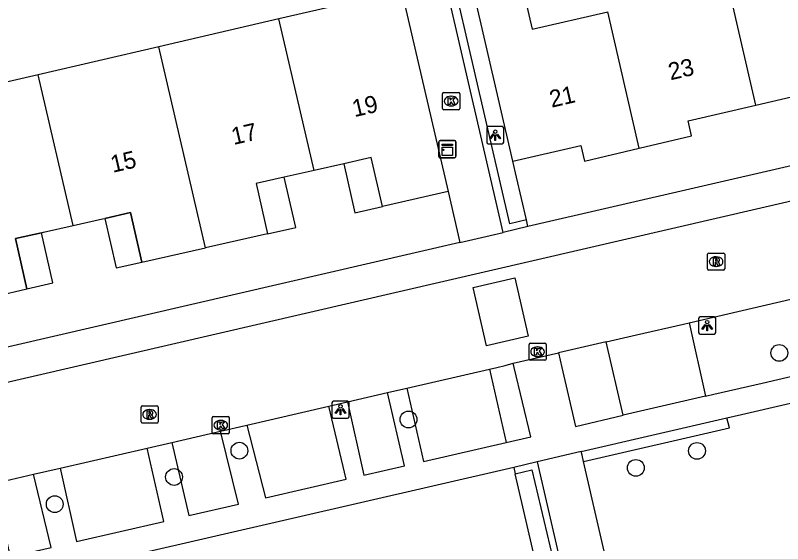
# Model space of a CAD drawing. Extents: x 156414 to 157775, y 382335 to 383765.
# Drawn here: x 156765.29 to 156810.03, y 382739.73 to 382770.51 of the extents above; entities that cross this region are included whole.
import ezdxf

# ---------------------------------------------------------------- set-up
doc = ezdxf.new("R2010")
doc.units = 0
for name, color, linetype in [('IMGEO_Boom', 7, 'Continuous'), ('IMGEO_Groenvoorziening', 7, 'Continuous'), ('IMGEO_Haag', 7, 'Continuous'), ('IMGEO_Kast', 7, 'Continuous'), ('IMGEO_Kolk', 7, 'Continuous'), ('IMGEO_Lichtpunt', 7, 'Continuous'), ('IMGEO_Muur', 7, 'Continuous'), ('IMGEO_Pand', 7, 'Continuous'), ('IMGEO_Pand_nummerreeks', 7, 'Continuous'), ('IMGEO_Pand_overbouw', 7, 'Continuous'), ('IMGEO_Parkeervlak_open', 7, 'Continuous'), ('IMGEO_Rijbaan_lokaal_gesloten', 7, 'Continuous'), ('IMGEO_Rijbaan_lokaal_open', 7, 'Continuous'), ('IMGEO_Rioolput', 7, 'Continuous'), ('IMGEO_Voetpad_open', 7, 'Continuous')]:
    doc.layers.add(name, color=color, linetype=linetype)

msp = doc.modelspace()

# ---------------------------------------------------------------- linework, layer by layer
at = {"layer": 'IMGEO_Boom'}
for centre in [(156809.836, 382750.839), (156788.215, 382746.96), (156778.352, 382745.143), (156805.037, 382745.131), (156801.469, 382744.14), (156774.54, 382743.611), (156767.583, 382742.024)]:
    msp.add_circle(centre, 0.489, dxfattribs=at)
at = {"layer": 'IMGEO_Groenvoorziening'}
for points in [[(156795.092, 382758.591), (156794.513, 382761.091), (156794.298, 382762.018)], [(156795.633, 382738.617), (156794.426, 382743.797)]]:
    msp.add_lwpolyline(points, dxfattribs=at)
at = {"layer": 'IMGEO_Haag'}
msp.add_lwpolyline([(156798.417, 382744.512), (156806.927, 382746.477), (156806.778, 382747.058)], dxfattribs=at)
at = {"layer": 'IMGEO_Kast'}
for p, q in [((156790.052, 382763.213), (156790.893, 382763.213)), ((156790.893, 382763.213), (156790.052, 382763.213)), ((156789.977, 382762.288), (156789.977, 382763.129)), ((156789.977, 382763.129), (156789.977, 382762.288)), ((156790.977, 382763.138), (156790.977, 382762.297)), ((156790.977, 382762.297), (156790.977, 382763.138)), ((156790.902, 382762.213), (156790.061, 382762.213)), ((156790.061, 382762.213), (156790.902, 382762.213))]:
    msp.add_line(p, q, dxfattribs=at)
for points in [[(156790.172, 382763.003), (156790.772, 382763.003), (156790.772, 382762.918), (156790.172, 382762.918), (156790.172, 382763.003)], [(156790.172, 382762.828), (156790.772, 382762.828), (156790.772, 382762.339), (156790.172, 382762.339), (156790.172, 382762.828)]]:
    msp.add_lwpolyline(points, dxfattribs=at)
msp.add_circle((156790.256, 382762.677), 0.0377, dxfattribs=at)
for centre, start, end in [((156790.055, 382763.135), 92.4484, 184.2845), ((156790.055, 382763.135), 92.4484, 184.2845), ((156790.899, 382763.135), 2.4484, 94.2845), ((156790.899, 382763.135), 2.4484, 94.2845), ((156790.055, 382762.291), 182.4484, 274.2845), ((156790.055, 382762.291), 182.4484, 274.2845), ((156790.899, 382762.291), 272.4484, 4.2845), ((156790.899, 382762.291), 272.4484, 4.2845)]:
    msp.add_arc(centre, 0.0779, start, end, dxfattribs=at)
at = {"layer": 'IMGEO_Kolk'}
for p, q in [((156790.199, 382765.088), (156790.199, 382765.94)), ((156790.274, 382766.014), (156791.126, 382766.014)), ((156791.2, 382765.94), (156791.2, 382765.088)), ((156790.687, 382765.794), (156790.712, 382765.794)), ((156791.126, 382765.014), (156790.274, 382765.014)), ((156790.71, 382765.234), (156790.685, 382765.234)), ((156795.243, 382750.484), (156795.243, 382751.336)), ((156795.318, 382751.41), (156796.17, 382751.41)), ((156795.731, 382751.19), (156795.756, 382751.19)), ((156796.244, 382751.336), (156796.244, 382750.484)), ((156796.17, 382750.41), (156795.318, 382750.41)), ((156795.754, 382750.63), (156795.729, 382750.63)), ((156776.839, 382747.129), (156777.691, 382747.129)), ((156776.764, 382746.203), (156776.764, 382747.055)), ((156777.252, 382746.909), (156777.277, 382746.909)), ((156777.765, 382747.055), (156777.765, 382746.203)), ((156777.275, 382746.349), (156777.25, 382746.349)), ((156777.691, 382746.129), (156776.839, 382746.129))]:
    msp.add_line(p, q, dxfattribs=at)
for points in [[(156790.199, 382765.088), (156790.199, 382765.94)], [(156790.274, 382766.014), (156791.126, 382766.014)], [(156791.2, 382765.94), (156791.2, 382765.088)], [(156790.52, 382765.714), (156790.643, 382765.714), (156790.643, 382765.563), (156790.773, 382765.714), (156790.937, 382765.714), (156790.791, 382765.563), (156790.944, 382765.314), (156790.792, 382765.314), (156790.707, 382765.478), (156790.643, 382765.411), (156790.643, 382765.314), (156790.52, 382765.314), (156790.52, 382765.714)], [(156791.126, 382765.014), (156790.274, 382765.014)], [(156795.243, 382750.484), (156795.243, 382751.336)], [(156795.318, 382751.41), (156796.17, 382751.41)], [(156796.244, 382751.336), (156796.244, 382750.484)], [(156795.564, 382751.11), (156795.687, 382751.11), (156795.687, 382750.959), (156795.817, 382751.11), (156795.981, 382751.11), (156795.835, 382750.959), (156795.988, 382750.71), (156795.836, 382750.71), (156795.751, 382750.874), (156795.687, 382750.807), (156795.687, 382750.71), (156795.564, 382750.71), (156795.564, 382751.11)], [(156796.17, 382750.41), (156795.318, 382750.41)], [(156776.839, 382747.129), (156777.691, 382747.129)], [(156776.764, 382746.203), (156776.764, 382747.055)], [(156777.085, 382746.829), (156777.208, 382746.829), (156777.208, 382746.678), (156777.338, 382746.829), (156777.502, 382746.829), (156777.356, 382746.678), (156777.509, 382746.429), (156777.357, 382746.429), (156777.272, 382746.593), (156777.208, 382746.526), (156777.208, 382746.429), (156777.085, 382746.429), (156777.085, 382746.829)], [(156777.765, 382747.055), (156777.765, 382746.203)], [(156777.691, 382746.129), (156776.839, 382746.129)]]:
    msp.add_lwpolyline(points, dxfattribs=at)
for centre, start, end in [((156790.276, 382765.938), 91.552, 178.448), ((156790.276, 382765.938), 91.552, 178.448), ((156791.124, 382765.938), 1.552, 88.448), ((156791.124, 382765.938), 1.552, 88.448), ((156790.276, 382765.09), 181.552, 268.448), ((156790.276, 382765.09), 181.552, 268.448), ((156791.124, 382765.09), 271.552, 358.448), ((156791.124, 382765.09), 271.552, 358.448), ((156795.32, 382751.334), 91.552, 178.448), ((156795.32, 382751.334), 91.552, 178.448), ((156796.168, 382751.334), 1.552, 88.448), ((156796.168, 382751.334), 1.552, 88.448), ((156795.32, 382750.486), 181.552, 268.448), ((156795.32, 382750.486), 181.552, 268.448), ((156796.168, 382750.486), 271.552, 358.448), ((156796.168, 382750.486), 271.552, 358.448), ((156776.841, 382747.053), 91.552, 178.448), ((156776.841, 382747.053), 91.552, 178.448), ((156777.689, 382747.053), 1.552, 88.448), ((156777.689, 382747.053), 1.552, 88.448), ((156776.841, 382746.205), 181.552, 268.448), ((156776.841, 382746.205), 181.552, 268.448), ((156777.689, 382746.205), 271.552, 358.448), ((156777.689, 382746.205), 271.552, 358.448)]:
    msp.add_arc(centre, 0.0765, start, end, dxfattribs=at)
for centre, major_axis, ratio, start_param, end_param in [((156790.686, 382765.514), (-0.387, 0.002), 0.722429, 4.712389, 7.853982), ((156790.711, 382765.514), (-0.39, 0.002), 0.717154, 1.570796, 4.712389), ((156795.73, 382750.91), (-0.387, 0.002), 0.722429, 4.712389, 7.853982), ((156795.755, 382750.91), (-0.39, 0.002), 0.717154, 1.570796, 4.712389), ((156777.251, 382746.629), (-0.387, 0.002), 0.722429, 4.712389, 7.853982), ((156777.276, 382746.629), (-0.39, 0.002), 0.717154, 1.570796, 4.712389)]:
    msp.add_ellipse(centre, major_axis=major_axis, ratio=ratio, start_param=start_param, end_param=end_param, dxfattribs=at)
at = {"layer": 'IMGEO_Lichtpunt'}
for p, q in [((156792.773, 382763.934), (156792.773, 382763.127)), ((156792.773, 382763.934), (156792.773, 382763.127)), ((156793.675, 382764.029), (156792.867, 382764.029)), ((156793.675, 382764.029), (156792.867, 382764.029)), ((156793.769, 382763.127), (156793.769, 382763.934)), ((156793.769, 382763.127), (156793.769, 382763.934)), ((156792.867, 382763.033), (156793.675, 382763.033)), ((156792.867, 382763.033), (156793.675, 382763.033)), ((156806.032, 382752.935), (156805.224, 382752.935)), ((156806.032, 382752.935), (156805.224, 382752.935)), ((156805.13, 382752.84), (156805.13, 382752.033)), ((156805.13, 382752.84), (156805.13, 382752.033)), ((156806.126, 382752.033), (156806.126, 382752.84)), ((156806.126, 382752.033), (156806.126, 382752.84)), ((156805.224, 382751.939), (156806.032, 382751.939)), ((156805.224, 382751.939), (156806.032, 382751.939)), ((156784.653, 382748.025), (156783.845, 382748.025)), ((156784.653, 382748.025), (156783.845, 382748.025)), ((156783.751, 382747.93), (156783.751, 382747.123)), ((156783.751, 382747.93), (156783.751, 382747.123)), ((156784.747, 382747.123), (156784.747, 382747.93)), ((156784.747, 382747.123), (156784.747, 382747.93)), ((156783.845, 382747.029), (156784.653, 382747.029)), ((156783.845, 382747.029), (156784.653, 382747.029))]:
    msp.add_line(p, q, dxfattribs=at)
for points in [[(156793.147, 382763.598), (156793.186, 382763.57), (156792.998, 382763.308), (156792.96, 382763.335), (156793.147, 382763.598)], [(156793.249, 382763.55), (156793.296, 382763.55), (156793.296, 382763.228), (156793.249, 382763.228), (156793.249, 382763.55)], [(156793.359, 382763.57), (156793.397, 382763.597), (156793.584, 382763.335), (156793.545, 382763.307), (156793.359, 382763.57)], [(156805.504, 382752.504), (156805.543, 382752.476), (156805.355, 382752.214), (156805.317, 382752.241), (156805.504, 382752.504)], [(156805.716, 382752.476), (156805.754, 382752.503), (156805.941, 382752.241), (156805.902, 382752.213), (156805.716, 382752.476)], [(156805.606, 382752.456), (156805.653, 382752.456), (156805.653, 382752.134), (156805.606, 382752.134), (156805.606, 382752.456)], [(156784.125, 382747.594), (156784.164, 382747.566), (156783.976, 382747.304), (156783.938, 382747.331), (156784.125, 382747.594)], [(156784.337, 382747.566), (156784.375, 382747.593), (156784.562, 382747.331), (156784.523, 382747.303), (156784.337, 382747.566)], [(156784.227, 382747.546), (156784.274, 382747.546), (156784.274, 382747.224), (156784.227, 382747.224), (156784.227, 382747.546)]]:
    msp.add_lwpolyline(points, dxfattribs=at)
for centre in [(156793.272, 382763.732), (156805.629, 382752.638), (156784.25, 382747.728)]:
    msp.add_circle(centre, 0.0994, dxfattribs=at)
for centre, start, end in [((156792.867, 382763.934), 90, 180), ((156792.867, 382763.934), 90, 180), ((156793.675, 382763.934), 0, 90), ((156793.675, 382763.934), 0, 90), ((156792.867, 382763.127), 180, 270), ((156792.867, 382763.127), 180, 270), ((156793.675, 382763.127), 270, 0), ((156793.675, 382763.127), 270, 360), ((156805.224, 382752.84), 90, 180), ((156805.224, 382752.84), 90, 180), ((156806.032, 382752.84), 0, 90), ((156806.032, 382752.84), 0, 90), ((156805.224, 382752.033), 180, 270), ((156805.224, 382752.033), 180, 270), ((156806.032, 382752.033), 270, 0), ((156806.032, 382752.033), 270, 360), ((156783.845, 382747.93), 90, 180), ((156783.845, 382747.93), 90, 180), ((156784.653, 382747.93), 0, 90), ((156784.653, 382747.93), 0, 90), ((156783.845, 382747.123), 180, 270), ((156783.845, 382747.123), 180, 270), ((156784.653, 382747.123), 270, 0), ((156784.653, 382747.123), 270, 360)]:
    msp.add_arc(centre, 0.0946, start, end, dxfattribs=at)
at = {"layer": 'IMGEO_Muur'}
for points in [[(156793.73, 382757.867), (156788.095, 382782.246)], [(156795.092, 382758.591), (156794.115, 382758.365), (156788.665, 382781.967), (156789.639, 382782.192)], [(156795.182, 382758.201), (156795.092, 382758.591)], [(156795.182, 382758.201), (156793.73, 382757.867)], [(156795.712, 382744.485), (156794.348, 382744.171)], [(156795.712, 382744.485), (156802.123, 382716.713)], [(156794.348, 382744.171), (156794.426, 382743.797)], [(156794.426, 382743.797), (156795.403, 382744.032), (156796.63, 382738.862), (156801.644, 382717.012), (156800.687, 382716.754)]]:
    msp.add_lwpolyline(points, dxfattribs=at)
at = {"layer": 'IMGEO_Pand'}
for points in [[(156808.465, 382765.285), (156803.731, 382785.854)], [(156794.298, 382762.018), (156789.639, 382782.192)], [(156798.152, 382778.021), (156793.731, 382777), (156795.417, 382769.7), (156799.838, 382770.721)], [(156787.812, 382771.96), (156780.656, 382770.302)], [(156787.812, 382771.96), (156790.521, 382760.248)], [(156801.673, 382762.772), (156799.838, 382770.721)], [(156780.656, 382770.302), (156773.645, 382768.679)], [(156782.711, 382761.473), (156780.656, 382770.302)], [(156773.645, 382768.679), (156766.618, 382767.051)], [(156776.368, 382756.96), (156773.645, 382768.679)], [(156766.618, 382767.051), (156759.61, 382765.428)], [(156768.655, 382758.262), (156766.618, 382767.051)], [(156808.465, 382765.285), (156812.377, 382766.187), (156812.574, 382765.333), (156815.677, 382766.023)], [(156801.673, 382762.772), (156804.719, 382763.487), (156804.515, 382764.374), (156808.465, 382765.285)], [(156794.298, 382762.018), (156798.272, 382762.934), (156798.482, 382762.023), (156801.673, 382762.772)], [(156790.521, 382760.248), (156786.695, 382759.366), (156786.046, 382762.23), (156784.436, 382761.865), (156782.711, 382761.473)], [(156782.711, 382761.473), (156780.967, 382761.077), (156779.327, 382760.705), (156779.993, 382757.773), (156776.368, 382756.96)], [(156768.655, 382758.262), (156770.374, 382758.652), (156770.502, 382758.681), (156772.011, 382759.024), (156772.667, 382756.13), (156776.368, 382756.96)], [(156762.316, 382753.727), (156765.958, 382754.567), (156765.292, 382757.499), (156766.813, 382757.844), (156766.92, 382757.868), (156768.655, 382758.262)]]:
    msp.add_lwpolyline(points, dxfattribs=at)
at = {"layer": 'IMGEO_Pand_overbouw'}
for points in [[(156786.695, 382759.366), (156786.046, 382762.23), (156784.436, 382761.865), (156785.087, 382758.995)], [(156781.634, 382758.141), (156780.967, 382761.077), (156779.327, 382760.705), (156779.993, 382757.773)], [(156772.667, 382756.13), (156772.011, 382759.024), (156770.502, 382758.681), (156771.159, 382755.792)], [(156767.478, 382754.918), (156766.813, 382757.844), (156765.292, 382757.499), (156765.958, 382754.567)]]:
    msp.add_lwpolyline(points, close=True, dxfattribs=at)
at = {"layer": 'IMGEO_Parkeervlak_open'}
for points in [[(156804.584, 382752.601), (156805.537, 382748.317)], [(156800.741, 382747.207), (156799.739, 382751.484)], [(156792.936, 382749.902), (156793.904, 382745.624)]]:
    msp.add_lwpolyline(points, dxfattribs=at)
at = {"layer": 'IMGEO_Rijbaan_lokaal_gesloten'}
for points in [[(156721.265, 382739.07), (156830.11, 382764.227), (156940.449, 382789.73)], [(156804.584, 382752.601), (156810.513, 382753.968)], [(156799.739, 382751.484), (156801.515, 382751.894), (156804.246, 382752.523), (156804.584, 382752.601)], [(156799.739, 382751.484), (156796.957, 382750.843)], [(156794.325, 382750.236), (156796.957, 382750.843)], [(156788.11, 382748.789), (156792.936, 382749.902)], [(156792.936, 382749.902), (156793.365, 382750), (156793.859, 382750.113), (156794.325, 382750.236)], [(156784.651, 382747.991), (156786.985, 382748.529)], [(156786.985, 382748.529), (156788.11, 382748.789)], [(156778.791, 382746.639), (156783.567, 382747.741)], [(156783.567, 382747.741), (156784.651, 382747.991)], [(156774.409, 382745.628), (156777.247, 382746.283)], [(156777.247, 382746.283), (156778.791, 382746.639)], [(156772.97, 382745.297), (156774.409, 382745.628)], [(156767.902, 382744.128), (156772.97, 382745.297)], [(156766.346, 382743.769), (156767.902, 382744.128)], [(156764.008, 382743.229), (156766.346, 382743.769)]]:
    msp.add_lwpolyline(points, dxfattribs=at)
at = {"layer": 'IMGEO_Rijbaan_lokaal_open'}
msp.add_lwpolyline([(156791.982, 382754.654), (156794.416, 382755.212), (156795.196, 382751.813), (156792.762, 382751.255), (156791.982, 382754.654)], dxfattribs=at)
at = {"layer": 'IMGEO_Rioolput'}
for p, q in [((156805.651, 382755.734), (156805.651, 382756.586)), ((156805.726, 382756.66), (156806.578, 382756.66)), ((156806.652, 382756.586), (156806.652, 382755.734)), ((156806.139, 382756.44), (156806.164, 382756.44)), ((156806.578, 382755.66), (156805.726, 382755.66)), ((156806.162, 382755.88), (156806.137, 382755.88)), ((156772.615, 382746.828), (156772.615, 382747.68)), ((156772.69, 382747.754), (156773.542, 382747.754)), ((156773.616, 382747.68), (156773.616, 382746.828)), ((156773.103, 382747.534), (156773.128, 382747.534)), ((156773.542, 382746.754), (156772.69, 382746.754)), ((156773.126, 382746.974), (156773.101, 382746.974))]:
    msp.add_line(p, q, dxfattribs=at)
for points in [[(156805.651, 382755.734), (156805.651, 382756.586)], [(156805.726, 382756.66), (156806.578, 382756.66)], [(156806.652, 382756.586), (156806.652, 382755.734)], [(156806.24, 382756.358), (156805.988, 382756.36), (156805.988, 382755.96)], [(156805.988, 382755.96), (156806.112, 382755.96), (156806.112, 382756.122), (156806.123, 382756.122)], [(156806.166, 382756.279), (156806.112, 382756.279), (156806.112, 382756.198)], [(156806.112, 382756.198), (156806.164, 382756.198)], [(156806.17, 382756.093), (156806.241, 382755.96), (156806.381, 382755.96), (156806.316, 382756.086)], [(156806.578, 382755.66), (156805.726, 382755.66)], [(156772.615, 382746.828), (156772.615, 382747.68)], [(156772.69, 382747.754), (156773.542, 382747.754)], [(156773.616, 382747.68), (156773.616, 382746.828)], [(156773.204, 382747.452), (156772.952, 382747.454), (156772.952, 382747.054)], [(156772.952, 382747.054), (156773.076, 382747.054), (156773.076, 382747.216), (156773.087, 382747.216)], [(156773.13, 382747.373), (156773.076, 382747.373), (156773.076, 382747.292)], [(156773.076, 382747.292), (156773.128, 382747.292)], [(156773.134, 382747.187), (156773.205, 382747.054), (156773.345, 382747.054), (156773.28, 382747.18)], [(156773.542, 382746.754), (156772.69, 382746.754)]]:
    msp.add_lwpolyline(points, dxfattribs=at)
for centre, radius, start, end in [((156805.728, 382756.584), 0.0765, 91.552, 178.448), ((156805.728, 382756.584), 0.0765, 91.552, 178.448), ((156806.576, 382756.584), 0.0765, 1.552, 88.448), ((156806.576, 382756.584), 0.0765, 1.552, 88.448), ((156806.122, 382756.069), 0.0533, 26.0293, 88.6989), ((156806.148, 382756.387), 0.19, 274.7715, 282.9687), ((156806.172, 382756.183), 0.0964, 77.0061, 93.1865), ((156806.186, 382756.24), 0.0378, 276.6634, 79.6772), ((156806.239, 382756.248), 0.109, 350.3612, 89.416), ((156806.237, 382756.248), 0.112, 277.5842, 350.9817), ((156806.221, 382756.033), 0.108, 29.5134, 73.7905), ((156805.728, 382755.736), 0.0765, 181.552, 268.448), ((156805.728, 382755.736), 0.0765, 181.552, 268.448), ((156806.576, 382755.736), 0.0765, 271.552, 358.448), ((156806.576, 382755.736), 0.0765, 271.552, 358.448), ((156772.692, 382747.678), 0.0765, 91.552, 178.448), ((156772.692, 382747.678), 0.0765, 91.552, 178.448), ((156773.54, 382747.678), 0.0765, 1.552, 88.448), ((156773.54, 382747.678), 0.0765, 1.552, 88.448), ((156773.086, 382747.163), 0.0533, 26.0293, 88.6989), ((156773.112, 382747.481), 0.19, 274.7715, 282.9687), ((156773.136, 382747.277), 0.0964, 77.0061, 93.1865), ((156773.15, 382747.334), 0.0378, 276.6634, 79.6772), ((156773.203, 382747.342), 0.109, 350.3612, 89.416), ((156773.201, 382747.342), 0.112, 277.5842, 350.9817), ((156773.185, 382747.127), 0.108, 29.5134, 73.7905), ((156772.692, 382746.83), 0.0765, 181.552, 268.448), ((156772.692, 382746.83), 0.0765, 181.552, 268.448), ((156773.54, 382746.83), 0.0765, 271.552, 358.448), ((156773.54, 382746.83), 0.0765, 271.552, 358.448)]:
    msp.add_arc(centre, radius, start, end, dxfattribs=at)
for centre, major_axis, ratio, start_param, end_param in [((156806.138, 382756.16), (-0.387, 0.002), 0.722429, 4.712389, 7.853982), ((156806.163, 382756.16), (-0.39, 0.002), 0.717154, 1.570796, 4.712389), ((156773.102, 382747.254), (-0.387, 0.002), 0.722429, 4.712389, 7.853982), ((156773.127, 382747.254), (-0.39, 0.002), 0.717154, 1.570796, 4.712389)]:
    msp.add_ellipse(centre, major_axis=major_axis, ratio=ratio, start_param=start_param, end_param=end_param, dxfattribs=at)
at = {"layer": 'IMGEO_Voetpad_open'}
for points in [[(156865.597, 382774.441), (156795.182, 382758.201)], [(156790.521, 382760.248), (156791.208, 382757.283)], [(156791.208, 382757.283), (156793.73, 382757.867)], [(156791.208, 382757.283), (156759.674, 382750), (156720.792, 382741.02)], [(156796.957, 382750.843), (156797.151, 382750), (156797.944, 382746.56), (156800.741, 382747.207)], [(156793.904, 382745.624), (156795.357, 382745.959), (156794.382, 382750), (156794.325, 382750.236)], [(156805.537, 382748.317), (156806.026, 382748.43), (156808.846, 382749.082), (156811.571, 382749.713)], [(156784.651, 382747.991), (156785.611, 382743.712), (156787.985, 382744.259), (156786.985, 382748.529)], [(156788.11, 382748.789), (156789.094, 382744.515), (156793.904, 382745.624)], [(156805.537, 382748.317), (156800.741, 382747.207)], [(156806.778, 382747.058), (156807.635, 382747.256), (156812.585, 382748.399)], [(156778.791, 382746.639), (156779.866, 382742.388), (156784.587, 382743.476), (156783.567, 382747.741)], [(156798.282, 382745.097), (156806.778, 382747.058)], [(156774.409, 382745.628), (156775.402, 382741.359), (156778.299, 382742.027), (156777.247, 382746.283)], [(156767.902, 382744.128), (156768.858, 382739.85), (156773.943, 382741.023), (156772.97, 382745.297)], [(156798.282, 382745.097), (156795.712, 382744.485)], [(156798.417, 382744.512), (156798.332, 382744.878), (156798.282, 382745.097)], [(156803.492, 382722.496), (156798.417, 382744.512)], [(156794.348, 382744.171), (156723.806, 382727.923)], [(156764.008, 382743.229), (156764.993, 382738.959), (156767.373, 382739.508), (156766.346, 382743.769)]]:
    msp.add_lwpolyline(points, dxfattribs=at)

# ---------------------------------------------------------------- texts
at = {"layer": 'IMGEO_Pand_nummerreeks'}
for s, rotation, p in [('23', 12.9832, (156803.49, 382766.725)), ('21', 12.9832, (156796.558, 382765.126)), ('19', 12.9577, (156785.057, 382764.577)), ('17', 12.9577, (156778.012, 382762.956)), ('15', 12.9603, (156770.966, 382761.335))]:
    msp.add_text(s, height=1, rotation=rotation, dxfattribs=at).set_placement(p)

doc.saveas('drawing.dxf')
